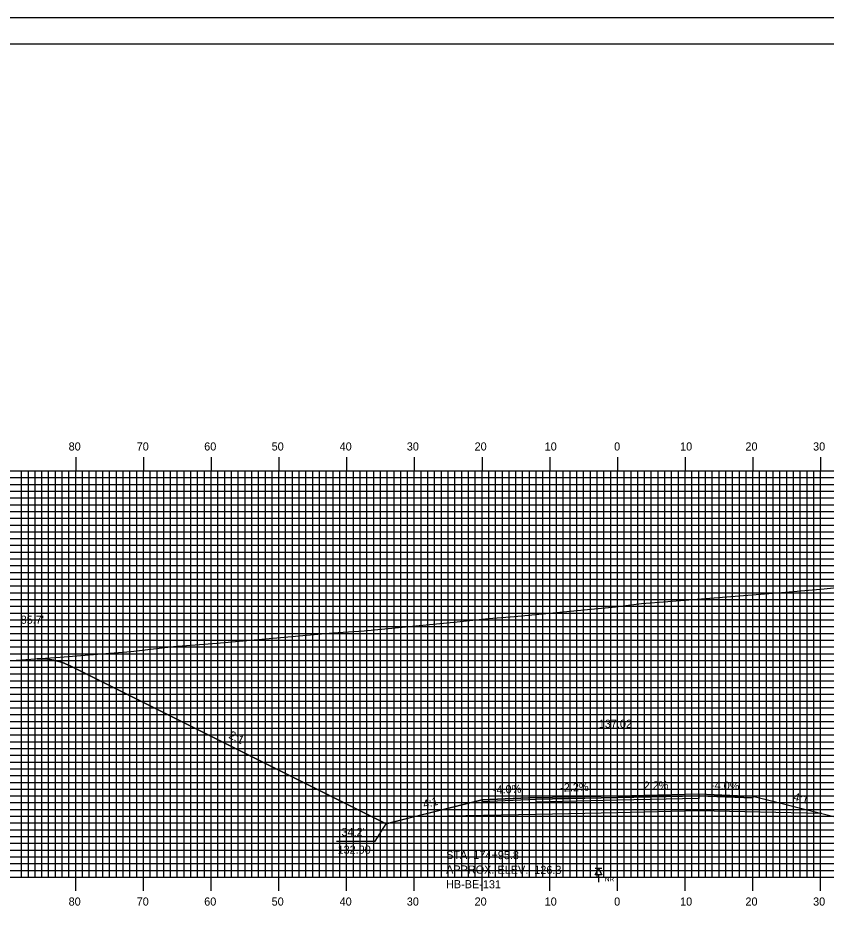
# Model space of a CAD drawing. Extents: x 1783828 to 1784171, y 442591 to 442811.
# Drawn here: x 1783905 to 1784024.3, y 442678.1 to 442810.5 of the extents above; entities that cross this region are included whole.
import ezdxf

# ---------------------------------------------------------------- set-up
doc = ezdxf.new("R2010")
doc.units = 0
for name, color, linetype in [('ANNOTATION', 7, 'Continuous'), ('BORDER', 7, 'Continuous'), ('BORING - NO REFUSAL', 7, 'Continuous'), ('D_Roadway_Centerline', 7, 'Continuous'), ('D_Roadway_Centerline_Text', 7, 'Continuous'), ('D_Roadway_Edge_Shoulder', 7, 'Continuous'), ('D_Roadway_Edge_TW', 7, 'Continuous'), ('D_Roadway_Pavement', 7, 'Continuous'), ('D_Roadway_SlopeLines', 7, 'Continuous'), ('D_Roadway_SubGrade', 7, 'Continuous'), ('D_Text_Standard', 7, 'Continuous'), ('H_V ANNOTATION', 7, 'Continuous'), ('MAJOR', 7, 'Continuous'), ('MINOR', 7, 'Continuous'), ('PLOT BOUNDARY', 7, 'Continuous'), ('S_Roadway_Centerline', 7, 'Continuous')]:
    doc.layers.add(name, color=color, linetype=linetype)

msp = doc.modelspace()

# ---------------------------------------------------------------- linework, layer by layer
at = {"layer": 'ANNOTATION'}
msp.add_lwpolyline([(1783952, 442689), (1783957.69, 442689), (1783959.31, 442691.56)], dxfattribs=at)
at = {"layer": 'BORDER'}
msp.add_lwpolyline([(1783843.89, 442596.67), (1784163.89, 442596.67), (1784163.89, 442806.67), (1783843.89, 442806.67)], close=True, dxfattribs=at)
at = {"layer": 'BORING - NO REFUSAL'}
for p, q in [((1783991.17, 442684.97), (1783990.21, 442684.97)), ((1783990.69, 442684.01), (1783990.69, 442682.95))]:
    msp.add_line(p, q, dxfattribs=at)
msp.add_lwpolyline([(1783990.69, 442684.97), (1783991.17, 442684.01), (1783990.21, 442684.01)], close=True, dxfattribs=at)
at = {"layer": 'D_Roadway_Centerline'}
msp.add_lwpolyline([(1783907.77, 442715.91), (1783909.02, 442715.91), (1783910.27, 442715.73), (1783911.52, 442715.37), (1783912.77, 442714.83), (1783959.31, 442691.56), (1783963.31, 442692.56), (1783973.49, 442695.11), (1783981.49, 442695.43), (1783993.49, 442695.69), (1784005.49, 442695.95), (1784013.49, 442695.63), (1784023.66, 442693.09), (1784026.24, 442692.45), (1784109.99, 442734.32), (1784111.24, 442734.89), (1784112.49, 442735.33), (1784113.74, 442735.65), (1784114.99, 442735.85)], dxfattribs=at)
at = {"layer": 'D_Roadway_Edge_Shoulder'}
for points in [[(1784005.49, 442695.95), (1784013.49, 442695.63), (1784013.49, 442695.38), (1784005.49, 442695.7)], [(1783981.49, 442695.43), (1783973.49, 442695.11), (1783973.49, 442694.86), (1783981.49, 442695.18)]]:
    msp.add_lwpolyline(points, close=True, dxfattribs=at)
at = {"layer": 'D_Roadway_Edge_TW'}
msp.add_lwpolyline([(1783981.49, 442695.18), (1783981.49, 442695.43), (1783993.49, 442695.69), (1784005.49, 442695.95), (1784005.49, 442695.7), (1783993.49, 442695.44)], close=True, dxfattribs=at)
at = {"layer": 'D_Roadway_Pavement'}
msp.add_lwpolyline([(1783981.49, 442694.76), (1783981.49, 442695.18), (1783993.49, 442695.44), (1784005.49, 442695.7), (1784005.49, 442695.29), (1783993.49, 442695.02)], close=True, dxfattribs=at)
at = {"layer": 'D_Roadway_SlopeLines'}
for points in [[(1783959.31, 442691.56), (1783912.77, 442714.83), (1783911.52, 442715.37), (1783910.27, 442715.73), (1783909.02, 442715.91), (1783907.77, 442715.91)], [(1783973.49, 442695.11), (1783959.31, 442691.56)], [(1784013.49, 442695.63), (1784026.24, 442692.45)]]:
    msp.add_lwpolyline(points, dxfattribs=at)
at = {"layer": 'D_Roadway_SubGrade'}
msp.add_lwpolyline([(1783981.49, 442692.93), (1783963.31, 442692.56), (1783973.49, 442695.11), (1783973.49, 442694.86), (1783981.49, 442695.18), (1783993.49, 442695.44), (1784005.49, 442695.7), (1784013.49, 442695.38), (1784013.49, 442695.63), (1784023.66, 442693.09), (1784005.49, 442693.45), (1783993.49, 442693.19)], close=True, dxfattribs=at)
at = {"layer": 'MAJOR'}
for p, q in [((1783913.49, 442745.67), (1783913.49, 442743.67)), ((1783923.49, 442745.67), (1783923.49, 442743.67)), ((1783933.49, 442745.67), (1783933.49, 442743.67)), ((1783943.49, 442745.67), (1783943.49, 442743.67)), ((1783953.49, 442745.67), (1783953.49, 442743.67)), ((1783963.49, 442745.67), (1783963.49, 442743.67)), ((1783973.49, 442745.67), (1783973.49, 442743.67)), ((1783983.49, 442745.67), (1783983.49, 442743.67)), ((1783993.49, 442745.67), (1783993.49, 442743.67)), ((1784003.49, 442745.67), (1784003.49, 442743.67)), ((1784013.49, 442745.67), (1784013.49, 442743.67)), ((1784023.49, 442745.67), (1784023.49, 442743.67)), ((1783853.49, 442743.67), (1784133.49, 442743.67)), ((1783853.49, 442743.67), (1784133.49, 442743.67)), ((1783913.49, 442683.67), (1783913.49, 442743.67)), ((1783923.49, 442683.67), (1783923.49, 442743.67)), ((1783933.49, 442683.67), (1783933.49, 442743.67)), ((1783943.49, 442683.67), (1783943.49, 442743.67)), ((1783953.49, 442683.67), (1783953.49, 442743.67)), ((1783963.49, 442683.67), (1783963.49, 442743.67)), ((1783973.49, 442683.67), (1783973.49, 442743.67)), ((1783983.49, 442683.67), (1783983.49, 442743.67)), ((1783993.49, 442683.67), (1783993.49, 442743.67)), ((1784003.49, 442683.67), (1784003.49, 442743.67)), ((1784013.49, 442683.67), (1784013.49, 442743.67)), ((1784023.49, 442683.67), (1784023.49, 442743.67)), ((1783853.49, 442738.67), (1784133.49, 442738.67)), ((1783853.49, 442733.67), (1784133.49, 442733.67)), ((1783853.49, 442728.67), (1784133.49, 442728.67)), ((1783853.49, 442723.67), (1784133.49, 442723.67)), ((1783853.49, 442718.67), (1784133.49, 442718.67)), ((1783853.49, 442713.67), (1784133.49, 442713.67)), ((1783853.49, 442708.67), (1784133.49, 442708.67)), ((1783853.49, 442703.67), (1784133.49, 442703.67)), ((1783853.49, 442698.67), (1784133.49, 442698.67)), ((1783853.49, 442693.67), (1784133.49, 442693.67)), ((1783853.49, 442688.67), (1784133.49, 442688.67)), ((1783853.49, 442683.67), (1784133.49, 442683.67)), ((1783853.49, 442683.67), (1784133.49, 442683.67)), ((1783913.49, 442681.66), (1783913.49, 442683.67)), ((1783923.49, 442681.66), (1783923.49, 442683.67)), ((1783933.49, 442681.66), (1783933.49, 442683.67)), ((1783943.49, 442681.66), (1783943.49, 442683.67)), ((1783953.49, 442681.66), (1783953.49, 442683.67)), ((1783963.49, 442681.66), (1783963.49, 442683.67)), ((1783973.49, 442681.66), (1783973.49, 442683.67)), ((1783983.49, 442681.66), (1783983.49, 442683.67)), ((1783993.49, 442681.66), (1783993.49, 442683.67)), ((1784003.49, 442681.66), (1784003.49, 442683.67)), ((1784013.49, 442681.66), (1784013.49, 442683.67)), ((1784023.49, 442681.66), (1784023.49, 442683.67))]:
    msp.add_line(p, q, dxfattribs=at)
at = {"layer": 'MINOR'}
for p, q in [((1783905.49, 442683.67), (1783905.49, 442743.67)), ((1783906.49, 442683.67), (1783906.49, 442743.67)), ((1783907.49, 442683.67), (1783907.49, 442743.67)), ((1783908.49, 442683.67), (1783908.49, 442743.67)), ((1783909.49, 442683.67), (1783909.49, 442743.67)), ((1783910.49, 442683.67), (1783910.49, 442743.67)), ((1783911.49, 442683.67), (1783911.49, 442743.67)), ((1783912.49, 442683.67), (1783912.49, 442743.67)), ((1783914.49, 442683.67), (1783914.49, 442743.67)), ((1783915.49, 442683.67), (1783915.49, 442743.67)), ((1783916.49, 442683.67), (1783916.49, 442743.67)), ((1783917.49, 442683.67), (1783917.49, 442743.67)), ((1783918.49, 442683.67), (1783918.49, 442743.67)), ((1783919.49, 442683.67), (1783919.49, 442743.67)), ((1783920.49, 442683.67), (1783920.49, 442743.67)), ((1783921.49, 442683.67), (1783921.49, 442743.67)), ((1783922.49, 442683.67), (1783922.49, 442743.67)), ((1783924.49, 442683.67), (1783924.49, 442743.67)), ((1783925.49, 442683.67), (1783925.49, 442743.67)), ((1783926.49, 442683.67), (1783926.49, 442743.67)), ((1783927.49, 442683.67), (1783927.49, 442743.67)), ((1783928.49, 442683.67), (1783928.49, 442743.67)), ((1783929.49, 442683.67), (1783929.49, 442743.67)), ((1783930.49, 442683.67), (1783930.49, 442743.67)), ((1783931.49, 442683.67), (1783931.49, 442743.67)), ((1783932.49, 442683.67), (1783932.49, 442743.67)), ((1783934.49, 442683.67), (1783934.49, 442743.67)), ((1783935.49, 442683.67), (1783935.49, 442743.67)), ((1783936.49, 442683.67), (1783936.49, 442743.67)), ((1783937.49, 442683.67), (1783937.49, 442743.67)), ((1783938.49, 442683.67), (1783938.49, 442743.67)), ((1783939.49, 442683.67), (1783939.49, 442743.67)), ((1783940.49, 442683.67), (1783940.49, 442743.67)), ((1783941.49, 442683.67), (1783941.49, 442743.67)), ((1783942.49, 442683.67), (1783942.49, 442743.67)), ((1783944.49, 442683.67), (1783944.49, 442743.67)), ((1783945.49, 442683.67), (1783945.49, 442743.67)), ((1783946.49, 442683.67), (1783946.49, 442743.67)), ((1783947.49, 442683.67), (1783947.49, 442743.67)), ((1783948.49, 442683.67), (1783948.49, 442743.67)), ((1783949.49, 442683.67), (1783949.49, 442743.67)), ((1783950.49, 442683.67), (1783950.49, 442743.67)), ((1783951.49, 442683.67), (1783951.49, 442743.67)), ((1783952.49, 442683.67), (1783952.49, 442743.67)), ((1783954.49, 442683.67), (1783954.49, 442743.67)), ((1783955.49, 442683.67), (1783955.49, 442743.67)), ((1783956.49, 442683.67), (1783956.49, 442743.67)), ((1783957.49, 442683.67), (1783957.49, 442743.67)), ((1783958.49, 442683.67), (1783958.49, 442743.67)), ((1783959.49, 442683.67), (1783959.49, 442743.67)), ((1783960.49, 442683.67), (1783960.49, 442743.67)), ((1783961.49, 442683.67), (1783961.49, 442743.67)), ((1783962.49, 442683.67), (1783962.49, 442743.67)), ((1783964.49, 442683.67), (1783964.49, 442743.67)), ((1783965.49, 442683.67), (1783965.49, 442743.67)), ((1783966.49, 442683.67), (1783966.49, 442743.67)), ((1783967.49, 442683.67), (1783967.49, 442743.67)), ((1783968.49, 442683.67), (1783968.49, 442743.67)), ((1783969.49, 442683.67), (1783969.49, 442743.67)), ((1783970.49, 442683.67), (1783970.49, 442743.67)), ((1783971.49, 442683.67), (1783971.49, 442743.67)), ((1783972.49, 442683.67), (1783972.49, 442743.67)), ((1783974.49, 442683.67), (1783974.49, 442743.67)), ((1783975.49, 442683.67), (1783975.49, 442743.67)), ((1783976.49, 442683.67), (1783976.49, 442743.67)), ((1783977.49, 442683.67), (1783977.49, 442743.67)), ((1783978.49, 442683.67), (1783978.49, 442743.67)), ((1783979.49, 442683.67), (1783979.49, 442743.67)), ((1783980.49, 442683.67), (1783980.49, 442743.67)), ((1783981.49, 442683.67), (1783981.49, 442743.67)), ((1783982.49, 442683.67), (1783982.49, 442743.67)), ((1783984.49, 442683.67), (1783984.49, 442743.67)), ((1783985.49, 442683.67), (1783985.49, 442743.67)), ((1783986.49, 442683.67), (1783986.49, 442743.67)), ((1783987.49, 442683.67), (1783987.49, 442743.67)), ((1783988.49, 442683.67), (1783988.49, 442743.67)), ((1783989.49, 442683.67), (1783989.49, 442743.67)), ((1783990.49, 442683.67), (1783990.49, 442743.67)), ((1783991.49, 442683.67), (1783991.49, 442743.67)), ((1783992.49, 442683.67), (1783992.49, 442743.67)), ((1783994.49, 442683.67), (1783994.49, 442743.67)), ((1783995.49, 442683.67), (1783995.49, 442743.67)), ((1783996.49, 442683.67), (1783996.49, 442743.67)), ((1783997.49, 442683.67), (1783997.49, 442743.67)), ((1783998.49, 442683.67), (1783998.49, 442743.67)), ((1783999.49, 442683.67), (1783999.49, 442743.67)), ((1784000.49, 442683.67), (1784000.49, 442743.67)), ((1784001.49, 442683.67), (1784001.49, 442743.67)), ((1784002.49, 442683.67), (1784002.49, 442743.67)), ((1784004.49, 442683.67), (1784004.49, 442743.67)), ((1784005.49, 442683.67), (1784005.49, 442743.67)), ((1784006.49, 442683.67), (1784006.49, 442743.67)), ((1784007.49, 442683.67), (1784007.49, 442743.67)), ((1784008.49, 442683.67), (1784008.49, 442743.67)), ((1784009.49, 442683.67), (1784009.49, 442743.67)), ((1784010.49, 442683.67), (1784010.49, 442743.67)), ((1784011.49, 442683.67), (1784011.49, 442743.67)), ((1784012.49, 442683.67), (1784012.49, 442743.67)), ((1784014.49, 442683.67), (1784014.49, 442743.67)), ((1784015.49, 442683.67), (1784015.49, 442743.67)), ((1784016.49, 442683.67), (1784016.49, 442743.67)), ((1784017.49, 442683.67), (1784017.49, 442743.67)), ((1784018.49, 442683.67), (1784018.49, 442743.67)), ((1784019.49, 442683.67), (1784019.49, 442743.67)), ((1784020.49, 442683.67), (1784020.49, 442743.67)), ((1784021.49, 442683.67), (1784021.49, 442743.67)), ((1784022.49, 442683.67), (1784022.49, 442743.67)), ((1783853.49, 442742.67), (1784133.49, 442742.67)), ((1783853.49, 442741.67), (1784133.49, 442741.67)), ((1783853.49, 442740.67), (1784133.49, 442740.67)), ((1783853.49, 442739.67), (1784133.49, 442739.67)), ((1783853.49, 442737.67), (1784133.49, 442737.67)), ((1783853.49, 442736.67), (1784133.49, 442736.67)), ((1783853.49, 442735.67), (1784133.49, 442735.67)), ((1783853.49, 442734.67), (1784133.49, 442734.67)), ((1783853.49, 442732.67), (1784133.49, 442732.67)), ((1783853.49, 442731.67), (1784133.49, 442731.67)), ((1783853.49, 442730.67), (1784133.49, 442730.67)), ((1783853.49, 442729.67), (1784133.49, 442729.67)), ((1783853.49, 442727.67), (1784133.49, 442727.67)), ((1783853.49, 442726.67), (1784133.49, 442726.67)), ((1783853.49, 442725.67), (1784133.49, 442725.67)), ((1783853.49, 442724.67), (1784133.49, 442724.67)), ((1783853.49, 442722.67), (1784133.49, 442722.67)), ((1783853.49, 442721.67), (1784133.49, 442721.67)), ((1783853.49, 442720.67), (1784133.49, 442720.67)), ((1783853.49, 442719.67), (1784133.49, 442719.67)), ((1783853.49, 442717.67), (1784133.49, 442717.67)), ((1783853.49, 442716.67), (1784133.49, 442716.67)), ((1783853.49, 442715.67), (1784133.49, 442715.67)), ((1783853.49, 442714.67), (1784133.49, 442714.67)), ((1783853.49, 442712.67), (1784133.49, 442712.67)), ((1783853.49, 442711.67), (1784133.49, 442711.67)), ((1783853.49, 442710.67), (1784133.49, 442710.67)), ((1783853.49, 442709.67), (1784133.49, 442709.67)), ((1783853.49, 442707.67), (1784133.49, 442707.67)), ((1783853.49, 442706.67), (1784133.49, 442706.67)), ((1783853.49, 442705.67), (1784133.49, 442705.67)), ((1783853.49, 442704.67), (1784133.49, 442704.67)), ((1783853.49, 442702.67), (1784133.49, 442702.67)), ((1783853.49, 442701.67), (1784133.49, 442701.67)), ((1783853.49, 442700.67), (1784133.49, 442700.67)), ((1783853.49, 442699.67), (1784133.49, 442699.67)), ((1783853.49, 442697.67), (1784133.49, 442697.67)), ((1783853.49, 442696.67), (1784133.49, 442696.67)), ((1783853.49, 442695.67), (1784133.49, 442695.67)), ((1783853.49, 442694.67), (1784133.49, 442694.67)), ((1783853.49, 442692.67), (1784133.49, 442692.67)), ((1783853.49, 442691.67), (1784133.49, 442691.67)), ((1783853.49, 442690.67), (1784133.49, 442690.67)), ((1783853.49, 442689.67), (1784133.49, 442689.67)), ((1783853.49, 442687.67), (1784133.49, 442687.67)), ((1783853.49, 442686.67), (1784133.49, 442686.67)), ((1783853.49, 442685.67), (1784133.49, 442685.67)), ((1783853.49, 442684.67), (1784133.49, 442684.67))]:
    msp.add_line(p, q, dxfattribs=at)
at = {"layer": 'PLOT BOUNDARY'}
msp.add_lwpolyline([(1783827.7, 442590.55), (1784167.7, 442590.55), (1784167.7, 442810.55), (1783827.7, 442810.55)], close=True, dxfattribs=at)
at = {"layer": 'S_Roadway_Centerline'}
msp.add_lwpolyline([(1783853.49, 442711.87), (1783866.8, 442712.79), (1783873.47, 442713.23), (1783881.83, 442713.97), (1783888.58, 442714.48), (1783898.84, 442715.31), (1783911.18, 442716.14), (1783921.63, 442717.01), (1783927.95, 442717.72), (1783934.33, 442718.23), (1783951.44, 442719.75), (1783956.09, 442720.05), (1783969.81, 442721.39), (1783974.44, 442721.86), (1783978.27, 442722.15), (1783993.21, 442723.6), (1783997.05, 442724.08), (1784000.91, 442724.38), (1784017.73, 442725.69), (1784024.01, 442726.23), (1784032.25, 442727.12)], dxfattribs=at)

# ---------------------------------------------------------------- texts
at = {"layer": 'ANNOTATION'}
for s, rotation, p in [('2:1', 333.4349, (1783935.98, 442704.27)), ('-4.0%', 2.2906, (1783975.12, 442695.97)), ('-2.2%', 1.2603, (1783985.05, 442696.3)), ('2.2%', 1.2603, (1783997.37, 442696.58)), ('-4.0%', 357.7094, (1784007.28, 442696.68)), ('4:1', 345.9638, (1784019.37, 442695.02)), ('4:1', 14.0362, (1783964.93, 442693.83))]:
    msp.add_text(s, height=1.2, rotation=rotation, dxfattribs=at).set_placement(p)
for s, p in [("34.2'", (1783952.73, 442689.73)), ('132.90', (1783952.15, 442687.13))]:
    msp.add_text(s, height=1.2, dxfattribs=at).set_placement(p)
at = {"layer": 'BORING - NO REFUSAL'}
for s, p in [('STA. 174+95.8', (1783968.19, 442686.36)), ('APPROX. ELEV.  126.3', (1783968.18, 442684.2)), ('HB-BE-131', (1783968.17, 442682.04))]:
    msp.add_text(s, height=1.2, rotation=359.8142, dxfattribs=at).set_placement(p)
msp.add_text('NR', height=0.7, dxfattribs=at).set_placement((1783991.62, 442683.05))
at = {"layer": 'D_Roadway_Centerline'}
for s, p in [('C', (1783993.48, 442695.69)), ('L', (1783993.49, 442695.68))]:
    msp.add_text(s, height=0.0146, dxfattribs=at).set_placement(p)
at = {"layer": 'D_Roadway_Centerline_Text'}
msp.add_text('137.02', height=1.2, dxfattribs=at).set_placement((1783990.73, 442705.72))
at = {"layer": 'D_Text_Standard'}
msp.add_text("85.7'", height=1.2, dxfattribs=at).set_placement((1783905.35, 442721.09))
at = {"layer": 'H_V ANNOTATION'}
for s, p in [('80', (1783912.44, 442746.67)), ('70', (1783922.49, 442746.67)), ('60', (1783932.46, 442746.67)), ('50', (1783942.42, 442746.67)), ('40', (1783952.46, 442746.67)), ('30', (1783962.38, 442746.67)), ('20', (1783972.39, 442746.67)), ('10', (1783982.74, 442746.67)), ('0', (1783993, 442746.67)), ('10', (1784002.74, 442746.67)), ('20', (1784012.39, 442746.67)), ('30', (1784022.38, 442746.67)), ('80', (1783912.44, 442679.47)), ('70', (1783922.49, 442679.47)), ('60', (1783932.46, 442679.47)), ('50', (1783942.42, 442679.47)), ('40', (1783952.46, 442679.47)), ('30', (1783962.38, 442679.47)), ('20', (1783972.39, 442679.47)), ('10', (1783982.74, 442679.47)), ('0', (1783993, 442679.47)), ('10', (1784002.74, 442679.47)), ('20', (1784012.39, 442679.47)), ('30', (1784022.38, 442679.47))]:
    msp.add_text(s, height=1.2, dxfattribs=at).set_placement(p)

doc.saveas('drawing.dxf')
